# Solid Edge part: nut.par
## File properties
Author: Sarvanan
Template: sync ansi part.par
Last saved by: Cadcim
Revision: 4
Application: Solid Edge
Accuracy: 0.990
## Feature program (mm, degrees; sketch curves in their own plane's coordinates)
sketch for "Hole_1" plane through (27.3343, 36.5222, 2.54) normal (0, 0, 1) x-axis (1, 0, 0)
  hole centre (-0.0483, 0.0372) bore radius 3.302
hole "Hole_1" diameter 6.604 through
pattern "unnamed Pattern 1" of "Hole_1"
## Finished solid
Body 1: solid body, 11 faces, 22 edges, 12 vertices.
  Faces by surface: plane 8, cone 2, cylinder 1
  Edges by curve: intersection 12, line 6, circle 4
Bounding box of the edges (mm): 10.265 x 8.890 x 5.080, from (22.2017, 32.1144, -2.54) to (32.467, 41.0044, 2.54).
Cylindrical faces by radius (mm): R3.302 x1
Conical faces (half-angle, radius in mm at the cone's reference point): 45 deg R5.1326 x2
Planar faces by outward normal: +y 1, +z 1, -y 1, -z 1, oblique 4
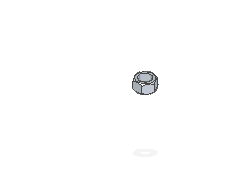
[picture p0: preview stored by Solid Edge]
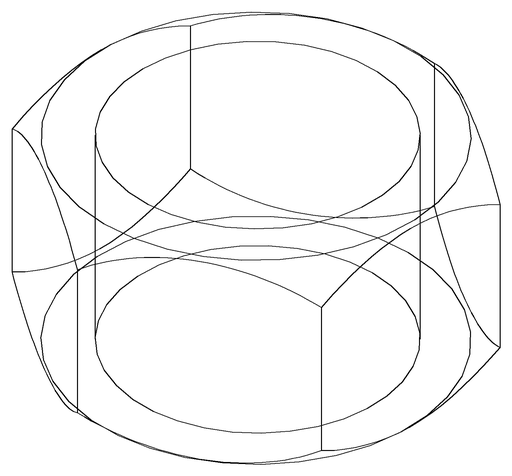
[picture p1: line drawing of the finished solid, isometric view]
